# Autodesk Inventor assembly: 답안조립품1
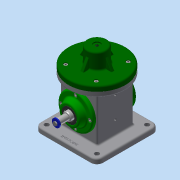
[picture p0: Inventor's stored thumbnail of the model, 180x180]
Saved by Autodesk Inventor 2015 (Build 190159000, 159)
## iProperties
Created: 2021-05
Part Number: 답안조립품1
Document SubType Name: Assembly
Designer: 101258642
Author: 101258642
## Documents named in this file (19)
- C:\Users\101258642\Desktop\710506V1010\답안조립품1.iam
- C:\Users\101258642\Desktop\710506V1010\본체.ipt
- C:\Users\101258642\Desktop\710506V1010\E-링.ipt
- C:\Users\101258642\Desktop\710506V1010\V-벨트풀리.ipt
- C:\Users\101258642\Desktop\710506V1010\덮개.ipt
- C:\Users\101258642\Desktop\710506V1010\뒤커버.ipt
- C:\Users\101258642\Desktop\710506V1010\링크.ipt
- C:\Users\101258642\Desktop\710506V1010\베어링 17 x 40 x 12.ipt
- C:\Users\101258642\Desktop\710506V1010\볼트 M4 x 10.ipt
- C:\Users\101258642\Desktop\710506V1010\볼트 M4 x 12.ipt
- 볼트 M4 x 12.ipt
- C:\Users\101258642\Desktop\710506V1010\슬라이더.ipt
- C:\Users\101258642\Desktop\710506V1010\앞커버.ipt
- C:\Users\101258642\Desktop\710506V1010\오일 실 17 30 8.ipt
- C:\Users\101258642\Desktop\710506V1010\와셔 4x16.ipt
- C:\Users\101258642\Desktop\710506V1010\클레비스 핀 6 x 22.ipt
- 클레비스 핀 6 x 22.ipt
- C:\Users\101258642\Desktop\710506V1010\키 4 x 4 x 12.ipt
- C:\Users\101258642\Desktop\710506V1010\편심축.ipt
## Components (3 placed, 2 different names)
1. E-링:1
2. V-벨트풀리:1
3. E-링:2
